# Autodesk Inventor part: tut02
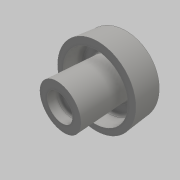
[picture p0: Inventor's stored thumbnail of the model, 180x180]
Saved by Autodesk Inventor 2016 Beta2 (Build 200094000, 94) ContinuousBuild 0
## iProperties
Created: 2015-02
Part Number: tut02
Material: Generic
Document SubType Name: Modeling
Designer: Sandeep
Density: 1 g/cm^3
Appearance: Default
Author: Sandeep
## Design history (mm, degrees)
revolve "Revolution1" stored, may be unused: angle "d12" = 20 deg
body "Solid1"
sketch "Sketch1"
  geometry: L1 (22, 0)-(0, 0); L2 (0, 0)-(0, 4); L3 (0, 4)-(-14, 4); L4 (-14, 4)-(-14, 8.5); L5 (-15.5, 10)-(-22, 10); L6 (-22, 10)-(-22, 16); L7 (-22, 16)-(15.5, 16); L8 (17, 17.5)-(17, 23); L9 (15, 25)-(2, 25); L10 (2, 25)-(2, 30); L11 (2, 30)-(22, 30); L12 (22, 30)-(22, 0); A1 r 2 centre (15, 23) between (17, 23) and (15, 25); A2 r 1.5 centre (-15.5, 8.5) between (-14, 8.5) and (-15.5, 10); A3 r 1.5 centre (15.5, 17.5) between (15.5, 16) and (17, 17.5); 1 further point
  constraints: 24 end point, 11 perpendicular, 6 point on circle, 6 tangent, 3 centre point, 1 coincident, 1 equal radius, 1 horizontal
  dimensions: "d0" = 8 diameter of L3 L1; "d1" = 20 diameter of L5 L1; "d2" = 32 diameter of L7 L1; "d3" = 50 diameter of L9 L1; "d4" = 60 diameter of L11 L1; "d5" = 5 distance between parallel lines of L8 L12; "d6" = 20 distance of L10.end L11.end; "d7" = 22 distance of L1.start L1.end; "d8" = 36 distance between parallel lines of L4 L12; "d9" = 44 distance between parallel lines of L6 L12; "d10" = 2 radius of A1; "d11" = 1.5 radius of A2
